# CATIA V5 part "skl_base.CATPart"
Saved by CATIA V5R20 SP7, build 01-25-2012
Part number: skl_base
Publications: "Point.D", "Droite.1", "Point.E", "Droite.3", "Droite.4", "Point.D1", "Point.E1", "Droite.6", "Droite.7", "Droite.8"
Bounding box of the stored display mesh (mm): x 0 to 0, y 0 to 110, z -50 to 20
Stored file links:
  D:\IFMA\COURS\2A\projet balance IAO\catia\skl_base.CATPart
  D:\IFMA\COURS\2A\projet balance IAO\catia\Skl_projet_balance.CATProduct
  D:\IFMA\COURS\2A\projet balance IAO\catia\skl_barre_BC.CATPart
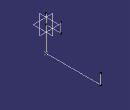
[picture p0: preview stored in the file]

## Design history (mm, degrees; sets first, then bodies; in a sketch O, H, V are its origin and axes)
Set1
  Point1 "Point.D": linked copy from another document
  Point2 "Point.E": linked copy from another document
  Point3 "Point.E'": linked copy from another document
  Point4 "Point.C": linked copy from another document
  Plane1 "Plan_socle_1": linked copy from another document
  Plane2 "Plan_socle_2": linked copy from another document
  Line1: linked copy from another document
  Point5 "Point.J": linked copy from another document
  Plane3 "Plan_socle_3": linked copy from another document
Body1 (main body)
  Point6 "Point.D": stored without definition
  Point7 "Point.E": stored without definition
  Line2: type PtPt, FirstPoint Point1, SecondPoint Point2
  Line3: type PtDir, RefPoint Point2, Direction xy-plane, Support yz-plane, Start 0, End 20
  Line4: type PtDir, RefPoint Point1, Direction xy-plane, Support yz-plane, Start 0, End 20
  Line5: type PtPt, FirstPoint Point2, SecondPoint Point3
  Line6: type PtPt, FirstPoint Point3, SecondPoint Point4
  Line7: type PtDir, RefPoint Point4, Direction xy-plane, Start 0, End 20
